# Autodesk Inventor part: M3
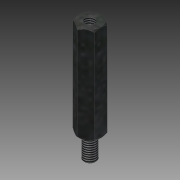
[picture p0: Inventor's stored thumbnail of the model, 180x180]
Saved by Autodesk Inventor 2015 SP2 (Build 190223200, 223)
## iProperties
Created: 2012-08
Part Number: M3
Material: Stahl
Document SubType Name: Modeling
Designer: rYan
Density: 7.85 g/cm^3
Mass: 1.74537 g
Surface Area: 3.04272 cm^2
Volume: 0.22234 cm^3
Appearance: Platte
Author: rYan
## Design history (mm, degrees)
derived "Abstandsbolzen Typ B.ipt"
feature "Volumenkörper1::Abstandsbolzen Typ B.ipt"
tag "Bezeichnung1"
node "Volumenkörper1"
other parameters: "SW" = 5.5, "L" = 24, "d2" = 0, "l_" = 7, "d9" = 118 deg, "GA_" = 3, "A_" = 6, "d13" = 0, "d17" = 0.25, "d20" = 45 deg
